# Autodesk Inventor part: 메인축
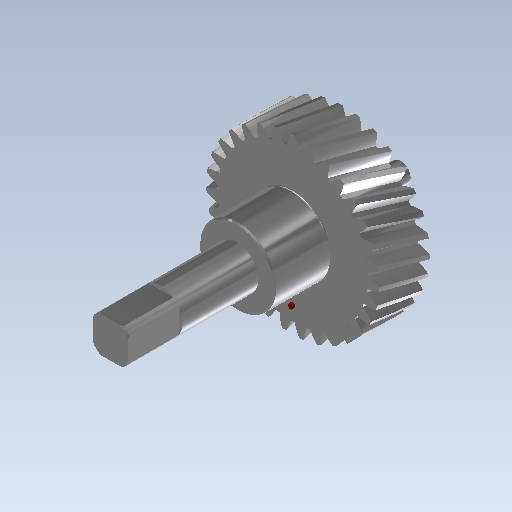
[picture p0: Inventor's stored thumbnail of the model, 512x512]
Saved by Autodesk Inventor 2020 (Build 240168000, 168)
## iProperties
CustomPartVersion: 1
Created: 2017-11
Part Number: 메인축
Material: 강철, 탄소
Document SubType Name: Modeling
Designer: mduedu
Categories: <?xml version="1.0" encoding="UTF-16"?> <MemberInstance><Categories><FamilyTemplate><FamilyTemplateParameter ValueType="xs:double" Id="1" ObjectReferenceKey="da
Density: 7.87 g/cm^3
Mass: 607.365 g
Surface Area: 183.17 cm^2
Volume: 77.1747 cm^3
Appearance: 반광택
Author: mduedu
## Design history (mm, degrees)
sketch "Sketch1"
  geometry: C1 r 34.094 at (0, 0)
  constraints: 1 centre point
  dimensions: "d0" = 68.18712 diameter of C1 (= da_da)
extrude "Extrusion1" new body sketch "Sketch1" distance "d1" = -20 (= da_b); taper "d2" = 0 deg
workplane "Work Plane2"
sketch "Sketch2"
  geometry: C1 r 34.094 at (0, 0) reference; C2 r 32.094 at (0, 0)
  constraints: 1 centre point, 1 coincident
  dimensions: "d3" = 64.18712 diameter of C2 (= da_dw)
feature "피치 지름" sketch "Sketch2" dims "d4" = 10, "d5" = 0
workplane "Work Plane8"
workplane "Work Plane9"
feature "스퍼 기어" dims "da_b" = -20, "da_d" = 64.18712, "da_aw" = 54.86964, "da_da" = 68.18712, "da_df" = 59.18712, "da_dw" = 64.18712, angle "da_beta" = 15 deg, "da_lefttooth" = 0, "da_righttooth" = 10
sketch "스케치3"
  geometry: C1 r 15 at (0, 0); 1 further point
  constraints: 1 centre point, 1 coincident
  dimensions: "d49" = 30 diameter of C1
extrude "돌출2" join sketch "스케치3" distance "d50" = 22; taper "d51" = 0 deg
sketch "스케치4"
  geometry: C1 r 8.5 at (0, 0); 1 further point
  constraints: 1 centre point, 1 coincident
  dimensions: "d52" = 17 diameter of C1
extrude "돌출3" join sketch "스케치4" distance "d53" = 50; taper "d54" = 0 deg
sketch "스케치5"
  geometry: C1 r 7.5 at (0, 0); 1 further point
  constraints: 1 centre point, 1 coincident
  dimensions: "d55" = 15 diameter of C1
extrude "돌출4" join sketch "스케치5" distance "d56" = 16; taper "d57" = 0 deg
sketch "스케치6"
  geometry: C1 r 4 at (0, 0); 1 further point
  constraints: 1 centre point, 1 coincident
  dimensions: "d58" = 8 diameter of C1
extrude "돌출5" join sketch "스케치6" distance "d59" = 7; taper "d60" = 0 deg
chamfer "모따기1" distance "d61" = 0.5; stored, may be unused: second distance "d62" = 2, angle "d63" = 45 deg
fillet "모깎기1" dims "d64" = 0.5
sketch "스케치7"
  geometry: L1 (-7, -7)-(7, -7); L2 (7, -7)-(7, 7); L3 (7, 7)-(-7, 7); L4 (-7, 7)-(-7, -7); L5 (-7, -7)-(7, 7); L6 (7, -7)-(-7, 7); L7 (-10, -10)-(10, -10); L8 (10, -10)-(10, 10); L9 (10, 10)-(-10, 10); L10 (-10, 10)-(-10, -10); L11 (-10, -10)-(10, 10); L12 (10, -10)-(-10, 10); 1 further point
  constraints: 24 end point, 4 equal length, 4 midpoint, 2 perpendicular, 1 horizontal, 1 vertical
  dimensions: "d65" = 14 distance of L3.end L2.end; "d66" = 14 distance of L2.end L1.end; "d67" = 20 distance of L9.end L8.end; "d68" = 20 distance of L8.end L7.end
extrude "돌출6" cut sketch "스케치7" distance "d69" = 20; taper "d70" = 0 deg
sketch "스케치8"
  geometry: C1 r 1 at (0, -24); 1 further point
  constraints: 1 centre point, 1 vertical alignment
  dimensions: "d71" = 2 diameter of C1; "d72" = 24 distance of point (0, 0) C1.centre
extrude "돌출7" join sketch "스케치8" distance "d73" = 1; taper "d74" = 0 deg
body "Solid1"
body "Srf1"
other parameters: "d16" = 54.86964 (= da_aw), "d17" = 0, "d34" = 1.01342 (computed from da_z), "d39" = 0, "d41" = 0, "d43" = 54.86964 (= da_aw), "d46" = 54.86964 (= da_aw), "d47" = 0, "d48" = 0
